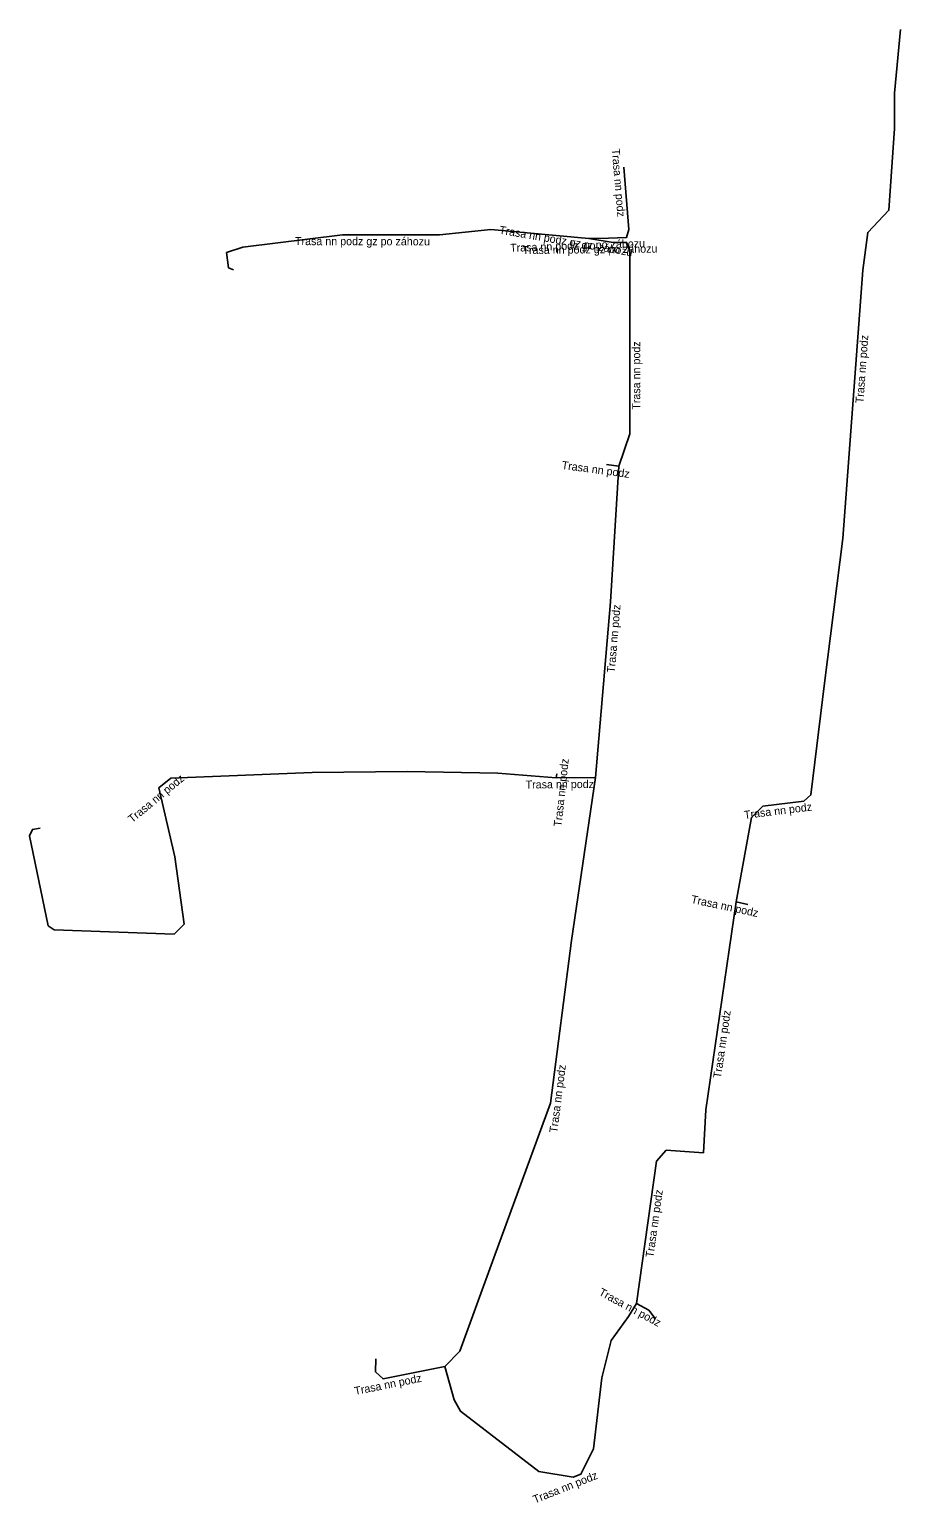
# Model space of a CAD drawing. Extents: x -600751 to -600543, y -1005171 to -1004662.
# Drawn here: x -600742.1 to -600687.7, y -1004753.7 to -1004661.7 of the extents above; entities that cross this region are included whole.
import ezdxf

# ---------------------------------------------------------------- set-up
doc = ezdxf.new("R2010")
doc.units = 0
doc.layers.add('Popiskový text - Ostatní atributy Trasy', color=7, linetype='Continuous')
doc.layers.add('Spojnice NN', color=7, linetype='Continuous')

msp = doc.modelspace()

# ---------------------------------------------------------------- linework, layer by layer
at = {"layer": 'Spojnice NN'}
for points in [[(-600692.41, -1004702.53), (-600691.25, -1004693.49), (-600690.01, -1004676.71), (-600689.7, -1004674.36), (-600688.38, -1004672.98), (-600688.02, -1004667.87), (-600688.03, -1004665.67), (-600687.65, -1004661.68)], [(-600704.95, -1004670.28), (-600704.62, -1004674.18)], [(-600707.12, -1004674.74), (-600713.25, -1004674.17), (-600716.45, -1004674.52), (-600722.52, -1004674.51), (-600728.75, -1004675.28), (-600729.76, -1004675.62), (-600729.64, -1004676.58), (-600729.34, -1004676.69)], [(-600707.12, -1004674.74), (-600705.9, -1004674.71), (-600704.77, -1004674.67), (-600704.62, -1004674.18)], [(-600705.6, -1004675), (-600707.12, -1004674.74)], [(-600704.56, -1004675.51), (-600704.77, -1004674.99), (-600705.6, -1004675)], [(-600704.56, -1004675.51), (-600704.57, -1004686.94), (-600705.25, -1004688.96)], [(-600705.25, -1004688.96), (-600705.78, -1004697.44), (-600706.71, -1004708.42)], [(-600705.25, -1004688.96), (-600706.03, -1004688.855)], [(-600697.93, -1004716.19), (-600696.97, -1004710.92), (-600696.25, -1004710.21), (-600693.7, -1004709.89), (-600693.25, -1004709.5), (-600692.41, -1004702.53)], [(-600709.16, -1004708.44), (-600712.81, -1004708.15), (-600718.48, -1004708.04), (-600724.41, -1004708.1), (-600733.25, -1004708.45), (-600733.99, -1004709.06), (-600732.99, -1004713.38), (-600732.42, -1004717.58), (-600733.04, -1004718.2), (-600740.53, -1004717.94), (-600740.91, -1004717.68), (-600742.08, -1004712.07), (-600741.89, -1004711.66), (-600741.414, -1004711.573)], [(-600709.16, -1004708.44), (-600709.132, -1004708.18)], [(-600706.71, -1004708.42), (-600708.2, -1004718.59), (-600709.52, -1004728.77), (-600713.07, -1004738.43), (-600715.19, -1004744.26), (-600716.13, -1004745.22)], [(-600706.71, -1004708.42), (-600709.16, -1004708.44)], [(-600699.97, -1004731.87), (-600699.81, -1004729.19), (-600697.93, -1004716.19)], [(-600697.93, -1004716.19), (-600697.186, -1004716.349)], [(-600704.15, -1004741.28), (-600702.9, -1004732.38), (-600702.29, -1004731.7), (-600699.97, -1004731.87)], [(-600716.13, -1004745.22), (-600715.54, -1004747.29), (-600715.15, -1004748.01), (-600710.26, -1004751.77), (-600708.1, -1004752.13), (-600707.62, -1004751.94), (-600706.84, -1004750.37), (-600706.31, -1004745.93), (-600705.73, -1004743.6), (-600704.65, -1004742.1), (-600704.15, -1004741.28)], [(-600704.15, -1004741.28), (-600703.37, -1004741.7), (-600702.986, -1004742.226)], [(-600716.13, -1004745.22), (-600719.98, -1004745.99), (-600720.45, -1004745.54), (-600720.428, -1004744.734)]]:
    msp.add_lwpolyline(points, dxfattribs=at)

# ---------------------------------------------------------------- texts
at = {"layer": 'Popiskový text - Ostatní atributy Trasy'}
for s, rotation, p in [('Trasa nn podz', 274.83658, (-600705.699, -1004669.149)), ('Trasa nn podz gz po záhozu', 350.29335, (-600712.756, -1004674.435)), ('Trasa nn podz gz po záhozu', 359.90561, (-600725.491, -1004675.155)), ('Trasa nn podz gz po záhozu', 2.02732, (-600712.04, -1004675.577)), ('Trasa nn podz gz po záhozu', 0.69028, (-600711.274, -1004675.719)), ('Trasa nn podz', 89.94987, (-600703.919, -1004685.439)), ('Trasa nn podz', 85.77367, (-600689.975, -1004685.048)), ('Trasa nn podz', 352.3332, (-600708.846, -1004689.132)), ('Trasa nn podz', 85.15863, (-600705.505, -1004701.889)), ('Trasa nn podz', 83.85337, (-600708.836, -1004711.509)), ('Trasa nn podz', 39.49959, (-600735.659, -1004711.278)), ('Trasa nn podz', 0.46771, (-600711.077, -1004709.106)), ('Trasa nn podz', 7.15267, (-600697.398, -1004711.009)), ('Trasa nn podz', 347.9368, (-600700.772, -1004716.248)), ('Trasa nn podz', 81.7712, (-600698.869, -1004727.227)), ('Trasa nn podz', 82.61191, (-600709.106, -1004730.634)), ('Trasa nn podz', 82.00514, (-600703.094, -1004738.434)), ('Trasa nn podz', 331.69924, (-600706.553, -1004740.725)), ('Trasa nn podz', 11.30993, (-600721.728, -1004747.002)), ('Trasa nn podz', 21.59531, (-600710.499, -1004753.779))]:
    msp.add_text(s, height=0.5, rotation=rotation, dxfattribs=at).set_placement(p)

doc.saveas('drawing.dxf')
